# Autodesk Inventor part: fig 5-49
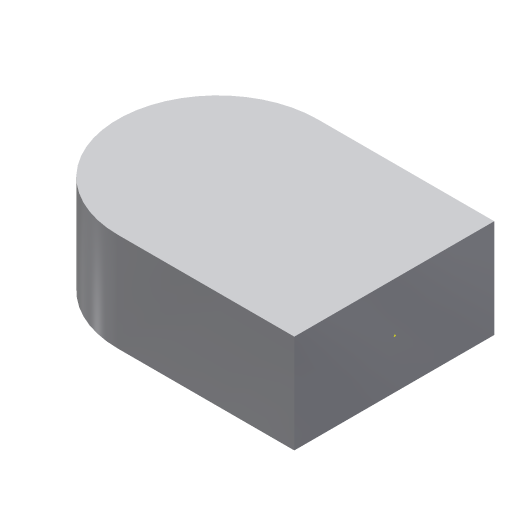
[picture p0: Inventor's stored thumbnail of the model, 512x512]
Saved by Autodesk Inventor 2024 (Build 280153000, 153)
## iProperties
Created: 2010-02
Part Number: fig 5-49
Document SubType Name: Modeling
Designer: CADSoft
Density: 1 g/cm^3
Material: Generic
Appearance: Default
Author: CADSoft
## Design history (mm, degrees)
sketch "Sketch1"
  geometry: L1 (-17.92, 20.292)-(0, 20.292); L2 (0, 20.292)-(0, 0); L3 (0, 0)-(-17.92, 0); A1 r 10.146 centre (-17.92, 10.146) between (-17.92, 20.292) and (-17.92, 0)
  constraints: 6 end point, 2 horizontal, 2 point on circle, 2 tangent, 1 centre point, 1 vertical
extrude "Extrusion1" new body sketch "Sketch1" distance "d0" = 10; taper "d1" = 0 deg
workpoint "Work Point1"
body "Solid1"
